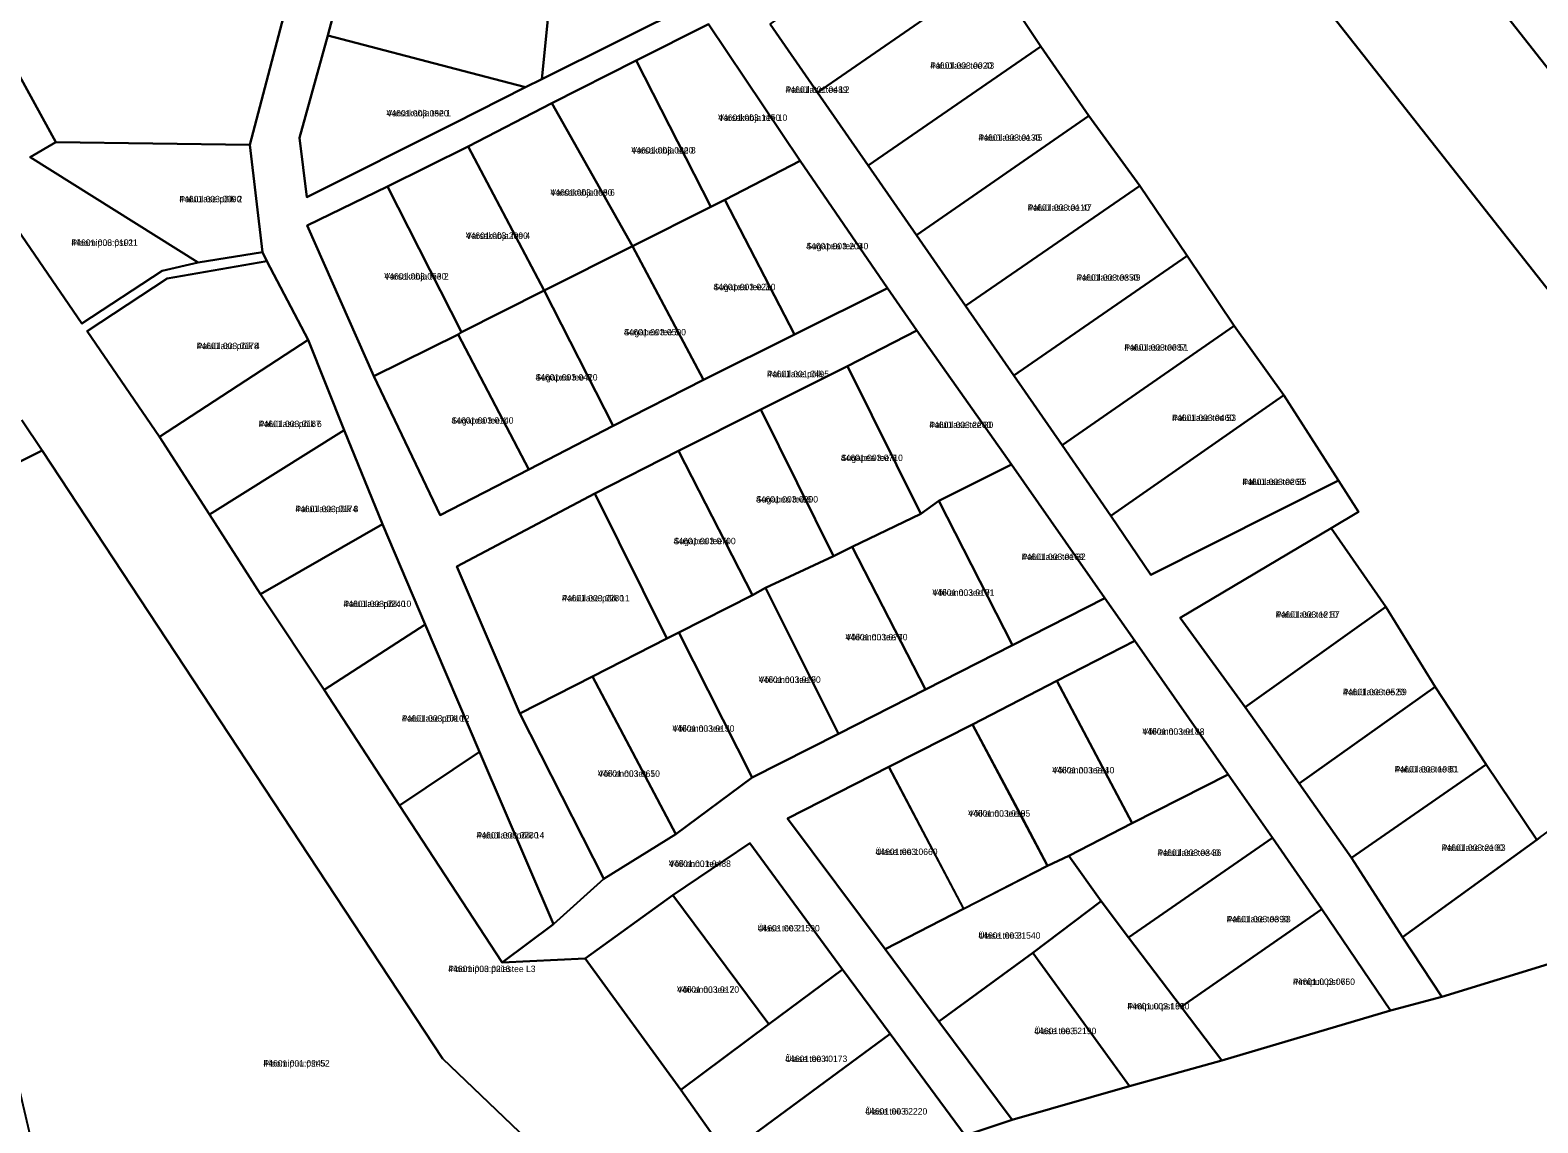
# Model space of a CAD drawing. Extents: x 551843 to 558501, y 6589003 to 6595718.
# Drawn here: x 553540.1 to 553892.5, y 6593798.2 to 6594053.6 of the extents above; entities that cross this region are included whole.
import ezdxf

# ---------------------------------------------------------------- set-up
doc = ezdxf.new("R2010")
doc.units = 0
for name, color, linetype in [('L_AADRESS', 7, 'Continuous'), ('PIIR', 7, 'Continuous'), ('TUNNUS', 7, 'Continuous')]:
    doc.layers.add(name, color=color, linetype=linetype)

msp = doc.modelspace()

# ---------------------------------------------------------------- linework, layer by layer
at = {"layer": 'PIIR'}
for points in [[(554441.09, 6593299.31), (554261.19, 6593527.78), (554141.98, 6593679.18), (554122.61, 6593703.78), (554013.74, 6593842.05), (553788.87, 6594127.63), (553766.28, 6594156.32), (553814.68, 6594146.58), (553836.64, 6594118.69), (553980.12, 6593936.47), (554062.14, 6593832.31), (554258.75, 6593582.61), (554309.59, 6593518.04), (554467.93, 6593316.95)], [(553892.97, 6593864.88), (553892.29, 6593864.39), (553880.45, 6593881.96), (553868.51, 6593900.1), (553857.01, 6593918.79), (553844.19, 6593937.25), (553850.61, 6593941.05), (553845.91, 6593948.34), (553833.12, 6593968.28), (553821.56, 6593984.48), (553810.54, 6594000.86), (553799.51, 6594017.22), (553787.57, 6594033.61), (553776.34, 6594049.78), (553764.77, 6594067.21), (553753.75, 6594083.63), (553742.72, 6594099.83), (553731.62, 6594116.26), (553721.36, 6594131.07), (553708.43, 6594145.93), (553788.87, 6594127.63), (554013.74, 6593842.05)], [(553615.73, 6594075.44), (553609.64, 6594052.38), (553603.07, 6594028.45), (553604.73, 6594014.55), (553639.11, 6594031.84), (553655.85, 6594040.27), (553659.7, 6594042.2), (553695.38, 6594059.93)], [(553698.63, 6594055.04), (553681.75, 6594046.52), (553662.01, 6594036.55), (553642.5, 6594026.43), (553623.58, 6594017.08), (553604.81, 6594007.97), (553620.45, 6593972.72), (553635.95, 6593940.23), (553656.68, 6593950.93), (553676.33, 6593961.17), (553697.49, 6593971.89), (553718.72, 6593982.45), (553740.52, 6593993.29), (553747.34, 6593983.4), (553731.11, 6593975.09), (553710.88, 6593964.97), (553691.64, 6593955.3), (553672.07, 6593945.34), (553639.84, 6593928.27), (553654.54, 6593893.89), (553674.15, 6593855.27), (553662.45, 6593844.66), (553645.13, 6593884.97), (553632.46, 6593914.73), (553622.47, 6593938.12), (553613.5, 6593960.12), (553605.06, 6593981.24), (553595.39, 6593999.6), (553594.41, 6594001.73), (553591.42, 6594026.8), (553600.85, 6594062.74)], [(553713.09, 6594055.03), (553724.14, 6594039.02), (553736, 6594021.96), (553747.31, 6594005.74), (553758.71, 6593989.19), (553770.02, 6593972.89), (553781.32, 6593956.58), (553792.68, 6593940.06), (553802.05, 6593926.33), (553845.91, 6593948.34), (553850.61, 6593941.05), (553844.19, 6593937.25), (553808.87, 6593916.22), (553824.08, 6593895.34), (553836.71, 6593877.56), (553848.98, 6593860.12), (553860.87, 6593841.59), (553870.08, 6593827.69), (553858.07, 6593824.49), (553842.01, 6593848.12), (553830.45, 6593864.83), (553820.09, 6593879.67), (553798.32, 6593910.89), (553791.28, 6593920.84), (553769.44, 6593952.07), (553747.34, 6593983.4), (553740.52, 6593993.29), (553720.07, 6594023.04), (553698.63, 6594055.04)], [(553520.12, 6594031.76), (553552.16, 6593985.04), (553570.97, 6593997.38), (553579.37, 6593999.32), (553594.41, 6594001.73), (553595.39, 6593999.6), (553572.1, 6593995.56), (553553.44, 6593983.25), (553570.3, 6593958.54), (553581.99, 6593940.44), (553593.91, 6593921.8), (553608.8, 6593899.44), (553626.41, 6593872.42), (553650.42, 6593835.7), (553669.81, 6593836.61), (553692.18, 6593805.9), (553702.89, 6593790.78)], [(553538.17, 6593962.48), (553542.86, 6593955.37), (553507.01, 6593937.53)], [(553668.84, 6593782.29), (553636.48, 6593813.23), (553542.86, 6593955.37), (553538.17, 6593962.48)], [(553758.61, 6593795.24), (553769.62, 6593798.93), (553797.08, 6593806.79), (553818.66, 6593812.78), (553858.07, 6593824.49), (553870.08, 6593827.69), (553909.89, 6593839.88), (553918.7, 6593842.58), (554046.25, 6593756.59)]]:
    msp.add_lwpolyline(points, dxfattribs=at)
for points in [[(553991.37, 6593974.95), (553980.12, 6593936.47), (553836.64, 6594118.69), (553883.5, 6594111.54), (553877.52, 6594090.46), (553906.3, 6594061.6), (553904.05, 6594050.84), (553942.36, 6594039.81), (553951.03, 6593995.91), (553962.77, 6593981.08)], [(553676.99, 6594087.38), (553695.38, 6594059.93), (553659.7, 6594042.2), (553662.14, 6594066.34), (553665.05, 6594095.15)], [(553596.23, 6594083.84), (553600.85, 6594062.74), (553591.42, 6594026.8), (553546.1, 6594027.45), (553537.6, 6594042.92), (553534.09, 6594049.22), (553535.15, 6594049.87), (553533.9, 6594052.21), (553526.78, 6594065.5), (553527.74, 6594065.97), (553546.27, 6594075.04), (553566.95, 6594081.08), (553572.4, 6594082.6), (553594.49, 6594083.76)], [(553713.09, 6594055.03), (553753.75, 6594083.63), (553764.77, 6594067.21), (553724.11, 6594039.02)], [(553615.73, 6594075.44), (553647.88, 6594069.14), (553662.14, 6594066.34), (553659.7, 6594042.2), (553655.85, 6594040.27), (553641.25, 6594044.1), (553609.64, 6594052.38)], [(553724.14, 6594039.02), (553764.77, 6594067.21), (553776.34, 6594049.78), (553736, 6594021.96)], [(553641.25, 6594044.1), (553655.85, 6594040.27), (553639.11, 6594031.84), (553604.73, 6594014.55), (553603.07, 6594028.45), (553609.64, 6594052.38)], [(553699.21, 6594012.33), (553681.75, 6594046.52), (553698.63, 6594055.04), (553720.07, 6594023.04), (553702.47, 6594013.97)], [(553776.34, 6594049.78), (553787.57, 6594033.61), (553747.31, 6594005.74), (553736, 6594021.96)], [(553680.9, 6594003.12), (553662.01, 6594036.55), (553681.75, 6594046.52), (553699.21, 6594012.33)], [(553520.12, 6594031.76), (553537.6, 6594042.92), (553546.1, 6594027.45), (553540.07, 6594023.91), (553579.37, 6593999.32), (553570.97, 6593997.38), (553552.16, 6593985.04)], [(553660.27, 6593992.77), (553642.5, 6594026.43), (553662.01, 6594036.55), (553680.9, 6594003.12)], [(553747.31, 6594005.74), (553787.57, 6594033.61), (553799.51, 6594017.22), (553758.71, 6593989.19)], [(553591.42, 6594026.8), (553594.41, 6594001.73), (553579.36, 6593999.33), (553540.11, 6594023.91), (553546.1, 6594027.45)], [(553640.93, 6593983.01), (553623.58, 6594017.08), (553642.5, 6594026.43), (553660.27, 6593992.77)], [(553718.72, 6593982.45), (553702.47, 6594013.97), (553720.07, 6594023.04), (553740.52, 6593993.29)], [(553620.45, 6593972.72), (553604.81, 6594007.97), (553623.58, 6594017.08), (553640.93, 6593983.01), (553640.1, 6593982.46)], [(553758.71, 6593989.19), (553799.51, 6594017.22), (553810.54, 6594000.86), (553770.02, 6593972.89)], [(553697.49, 6593971.89), (553680.9, 6594003.12), (553699.21, 6594012.33), (553702.47, 6594013.97), (553718.72, 6593982.45)], [(553676.33, 6593961.17), (553660.27, 6593992.77), (553680.9, 6594003.12), (553697.49, 6593971.89)], [(553553.44, 6593983.25), (553572.1, 6593995.56), (553595.39, 6593999.6), (553605.06, 6593981.24), (553570.3, 6593958.54)], [(553770.02, 6593972.89), (553810.54, 6594000.86), (553821.56, 6593984.48), (553781.32, 6593956.58)], [(553656.68, 6593950.93), (553640.1, 6593982.46), (553640.93, 6593983.01), (553660.27, 6593992.77), (553676.33, 6593961.17)], [(553635.95, 6593940.23), (553620.45, 6593972.72), (553640.1, 6593982.46), (553656.68, 6593950.93)], [(553747.34, 6593983.4), (553769.44, 6593952.07), (553752.48, 6593943.57), (553748.27, 6593940.55), (553731.11, 6593975.09)], [(553781.32, 6593956.58), (553821.56, 6593984.48), (553833.12, 6593968.28), (553792.68, 6593940.06)], [(553570.3, 6593958.54), (553605.06, 6593981.24), (553613.5, 6593960.12), (553581.99, 6593940.44)], [(553731.11, 6593975.09), (553748.27, 6593940.55), (553732.27, 6593932.82), (553727.85, 6593930.66), (553710.88, 6593964.97)], [(553792.68, 6593940.06), (553833.12, 6593968.28), (553845.91, 6593948.34), (553802.05, 6593926.33)], [(553710.88, 6593964.97), (553727.85, 6593930.66), (553711.99, 6593923.23), (553708.92, 6593921.58), (553691.64, 6593955.3)], [(553581.99, 6593940.44), (553613.5, 6593960.12), (553622.47, 6593938.12), (553593.91, 6593921.8)], [(553514.88, 6593903.23), (553507.01, 6593937.53), (553542.86, 6593955.37), (553636.48, 6593813.23), (553668.84, 6593782.29), (553682.2, 6593770.11), (553662.08, 6593754.91), (553645.43, 6593779.86), (553641.35, 6593785.23), (553628.15, 6593776.12), (553631.77, 6593770.74), (553620.41, 6593763.16), (553618.37, 6593761.87), (553614.56, 6593767.34), (553601.23, 6593758.1), (553604.99, 6593752.88), (553591.37, 6593743.76), (553608.02, 6593718.81), (553573.18, 6593693.61), (553568.93, 6593701.92), (553562.79, 6593698.22), (553544.92, 6593774.7), (553535.42, 6593815.33), (553523, 6593868.46)], [(553691.64, 6593955.3), (553708.92, 6593921.58), (553691.71, 6593912.82), (553688.94, 6593911.4), (553672.07, 6593945.34)], [(553752.48, 6593943.57), (553769.44, 6593952.07), (553791.28, 6593920.84), (553769.71, 6593909.88)], [(553672.07, 6593945.34), (553688.94, 6593911.4), (553671.57, 6593902.55), (553654.54, 6593893.89), (553639.84, 6593928.27)], [(553732.27, 6593932.82), (553748.27, 6593940.55), (553752.48, 6593943.57), (553769.71, 6593909.88), (553749.35, 6593899.48)], [(553622.47, 6593938.12), (553632.46, 6593914.73), (553608.8, 6593899.44), (553593.91, 6593921.8)], [(553824.08, 6593895.34), (553808.87, 6593916.22), (553844.19, 6593937.25), (553857.01, 6593918.79)], [(553727.85, 6593930.66), (553732.27, 6593932.82), (553749.35, 6593899.48), (553729.04, 6593889.13), (553711.99, 6593923.23)], [(553691.71, 6593912.82), (553708.92, 6593921.58), (553711.99, 6593923.23), (553729.04, 6593889.13), (553708.86, 6593878.97)], [(553650.42, 6593835.7), (553662.45, 6593844.66), (553674.15, 6593855.27), (553691.03, 6593865.68), (553708.86, 6593878.97), (553729.04, 6593889.13), (553749.35, 6593899.48), (553769.71, 6593909.88), (553791.28, 6593920.84), (553798.32, 6593910.89), (553780.06, 6593901.5), (553760.37, 6593891.35), (553740.8, 6593881.41), (553717.13, 6593869.32), (553739.93, 6593838.82), (553752.52, 6593821.87), (553769.62, 6593798.93), (553758.61, 6593795.24), (553741.11, 6593818.98), (553730.01, 6593834.09), (553708.34, 6593863.55), (553690.29, 6593851.46), (553669.81, 6593836.61)], [(553824.08, 6593895.34), (553857.01, 6593918.79), (553868.51, 6593900.1), (553836.71, 6593877.56)], [(553645.13, 6593884.97), (553626.41, 6593872.42), (553608.8, 6593899.44), (553632.46, 6593914.73)], [(553671.57, 6593902.55), (553688.94, 6593911.4), (553691.71, 6593912.82), (553708.86, 6593878.97), (553691.03, 6593865.68)], [(553798.32, 6593910.89), (553820.09, 6593879.67), (553797.66, 6593868.25), (553780.06, 6593901.5)], [(553671.57, 6593902.55), (553691.03, 6593865.68), (553674.15, 6593855.27), (553654.54, 6593893.89)], [(553780.06, 6593901.5), (553797.66, 6593868.25), (553782.9, 6593860.62), (553777.92, 6593858.3), (553760.37, 6593891.35)], [(553836.71, 6593877.56), (553868.51, 6593900.1), (553880.45, 6593881.96), (553848.98, 6593860.12)], [(553740.8, 6593881.41), (553760.37, 6593891.35), (553772.09, 6593869.27), (553777.89, 6593858.26), (553758.32, 6593848.22)], [(553645.13, 6593884.97), (553662.45, 6593844.66), (553650.42, 6593835.7), (553626.41, 6593872.42)], [(553740.8, 6593881.41), (553758.25, 6593848.21), (553739.93, 6593838.82), (553717.13, 6593869.32)], [(553790.43, 6593850.03), (553782.9, 6593860.62), (553797.66, 6593868.25), (553820.09, 6593879.67), (553830.45, 6593864.83), (553796.85, 6593841.55)], [(553848.98, 6593860.12), (553880.45, 6593881.96), (553892.29, 6593864.39), (553860.87, 6593841.59)], [(553870.08, 6593827.69), (553860.87, 6593841.59), (553892.29, 6593864.39), (553892.97, 6593864.88), (553900.13, 6593870.11), (553918.7, 6593842.58), (553909.89, 6593839.88)], [(553708.34, 6593863.55), (553730.01, 6593834.09), (553712.78, 6593821.28), (553690.29, 6593851.46)], [(553830.45, 6593864.83), (553842.01, 6593848.12), (553809.13, 6593825.35), (553796.85, 6593841.55)], [(553758.25, 6593848.21), (553777.92, 6593858.3), (553782.9, 6593860.62), (553790.43, 6593850.03), (553774.46, 6593837.94), (553752.52, 6593821.87), (553739.93, 6593838.82)], [(553690.29, 6593851.46), (553712.78, 6593821.28), (553692.18, 6593805.9), (553669.81, 6593836.61)], [(553790.43, 6593850.03), (553796.85, 6593841.55), (553809.13, 6593825.35), (553818.66, 6593812.78), (553797.08, 6593806.79), (553774.46, 6593837.94)], [(553858.07, 6593824.49), (553818.66, 6593812.78), (553809.13, 6593825.35), (553842.01, 6593848.12)], [(553774.46, 6593837.94), (553797.08, 6593806.79), (553769.62, 6593798.93), (553752.52, 6593821.87)], [(553692.18, 6593805.9), (553712.78, 6593821.28), (553730.01, 6593834.09), (553741.11, 6593818.98), (553702.89, 6593790.78)], [(553741.11, 6593818.98), (553758.61, 6593795.24), (553710.04, 6593781.31), (553702.89, 6593790.78)]]:
    msp.add_lwpolyline(points, close=True, dxfattribs=at)

# ---------------------------------------------------------------- texts
at = {"layer": 'L_AADRESS'}
for s, p in [('Paluülase tee 43', (553750.48, 6594044.59)), ('Paluülase tee L2', (553716.68, 6594038.96)), ('Varsakabja tee 1', (553623.39, 6594033.46)), ('Varsakabja tee 10', (553700.91, 6594032.41)), ('Paluülase tee 45', (553761.76, 6594027.76)), ('Varsakabja tee 8', (553680.61, 6594024.79)), ('Paluülase põik 2', (553574.96, 6594013.39)), ('Varsakabja tee 6', (553661.7, 6594014.94)), ('Paluülase tee 47', (553773.26, 6594011.4)), ('Varsakabja tee 4', (553641.93, 6594004.83)), ('Ploomipuu pst 21', (553549.74, 6594003.21)), ('Sugapea tee 9', (553721.5, 6594002.4)), ('Varsakabja tee 2', (553622.87, 6593995.33)), ('Paluülase tee 49', (553784.69, 6593995.05)), ('Sugapea tee 7', (553699.81, 6593992.84)), ('Sugapea tee 5', (553678.88, 6593982.28)), ('Paluülase põik 4', (553579.01, 6593979.07)), ('Paluülase tee 51', (553795.86, 6593978.72)), ('Sugapea tee 3', (553658.21, 6593971.73)), ('Paluülase põik', (553712.32, 6593972.5)), ('Paluülase tee 53', (553807.02, 6593962.27)), ('Paluülase põik 6', (553593.52, 6593960.84)), ('Sugapea tee 1', (553638.57, 6593961.64)), ('Paluülase tee 30', (553750.27, 6593960.61)), ('Sugapea tee 8', (553729.58, 6593952.91)), ('Paluülase tee 55', (553823.45, 6593947.3)), ('Sugapea tee 6', (553709.75, 6593943.21)), ('Paluülase põik 8', (553602.07, 6593940.96)), ('Sugapea tee 4', (553690.5, 6593933.46)), ('Paluülase tee 32', (553771.88, 6593929.78)), ('Paluülase põik 11', (553664.39, 6593920.09)), ('Võikannu tee 9', (553750.99, 6593921.41)), ('Paluülase põik 10', (553613.33, 6593918.78)), ('Paluülase tee 57', (553831.25, 6593916.29)), ('Võikannu tee 7', (553730.67, 6593911)), ('Võikannu tee 5', (553710.38, 6593901.05)), ('Paluülase tee 59', (553846.93, 6593898.17)), ('Paluülase põik 12', (553626.96, 6593891.99)), ('Võikannu tee 3', (553690.21, 6593889.64)), ('Võikannu tee 12', (553800.08, 6593888.93)), ('Võikannu tee 1', (553672.79, 6593879.1)), ('Võikannu tee 10', (553779.01, 6593879.89)), ('Paluülase tee 61', (553859.05, 6593880.11)), ('Võikannu tee 8', (553759.34, 6593869.79)), ('Paluülase põik 14', (553644.43, 6593864.68)), ('Ülase tee 1', (553737.69, 6593860.82)), ('Paluülase tee 36', (553803.63, 6593860.61)), ('Paluülase tee 63', (553870.03, 6593861.78)), ('Võikannu tee', (553689.38, 6593858.04)), ('Ülase tee 2', (553710.15, 6593842.95)), ('Paluülase tee 38', (553819.8, 6593845.09)), ('Ülase tee 3', (553761.74, 6593841.25)), ('Ploomipuu puiestee L3', (553637.82, 6593833.45)), ('Võikannu tee 2', (553691.3, 6593828.61)), ('Pirnipuu pst 65', (553835.26, 6593830.45)), ('Pirnipuu pst 63', (553796.56, 6593824.72)), ('Ülase tee 5', (553774.8, 6593818.94)), ('Ploomipuu pst 52', (553594.61, 6593811.37)), ('Ülase tee 4', (553716.59, 6593812.44)), ('Ülase tee 6', (553735.29, 6593800.15))]:
    msp.add_text(s, height=1.5, dxfattribs=at).set_placement(p)
at = {"layer": 'TUNNUS'}
for s, p in [('44601:003:0020', (553750.48, 6594044.59)), ('44601:001:0489', (553716.68, 6594038.96)), ('44601:003:0820', (553623.39, 6594033.46)), ('44601:003:1150', (553700.91, 6594032.41)), ('44601:003:0130', (553761.76, 6594027.76)), ('44601:003:0220', (553680.61, 6594024.79)), ('44601:003:0090', (553574.96, 6594013.39)), ('44601:003:0080', (553661.7, 6594014.94)), ('44601:003:0110', (553773.26, 6594011.4)), ('44601:003:2090', (553641.93, 6594004.83)), ('44601:003:0191', (553549.74, 6594003.21)), ('44601:003:2040', (553721.5, 6594002.4)), ('44601:003:0530', (553622.87, 6593995.33)), ('44601:003:0350', (553784.69, 6593995.05)), ('44601:003:0210', (553699.81, 6593992.84)), ('44601:003:0500', (553678.88, 6593982.28)), ('44601:003:0178', (553579.01, 6593979.07)), ('44601:003:0087', (553795.86, 6593978.72)), ('44601:003:0420', (553658.21, 6593971.73)), ('44601:001:0495', (553712.32, 6593972.5)), ('44601:003:0460', (553807.02, 6593962.27)), ('44601:003:0187', (553593.52, 6593960.84)), ('44601:003:0140', (553638.57, 6593961.64)), ('44601:003:2200', (553750.27, 6593960.61)), ('44601:003:0710', (553729.58, 6593952.91)), ('44601:003:0260', (553823.45, 6593947.3)), ('44601:003:0200', (553709.75, 6593943.21)), ('44601:003:0174', (553602.07, 6593940.96)), ('44601:003:0700', (553690.5, 6593933.46)), ('44601:003:0169', (553771.88, 6593929.78)), ('44601:003:0280', (553664.39, 6593920.09)), ('44601:003:0171', (553750.99, 6593921.41)), ('44601:003:0240', (553613.33, 6593918.78)), ('44601:003:1210', (553831.25, 6593916.29)), ('44601:003:0740', (553730.67, 6593911)), ('44601:003:0190', (553710.38, 6593901.05)), ('44601:003:0520', (553846.93, 6593898.17)), ('44601:003:1010', (553626.96, 6593891.99)), ('44601:003:0150', (553690.21, 6593889.64)), ('44601:003:0188', (553800.08, 6593888.93)), ('44601:003:0650', (553672.79, 6593879.1)), ('44601:003:2240', (553779.01, 6593879.89)), ('44601:003:1980', (553859.05, 6593880.11)), ('44601:003:0195', (553759.34, 6593869.79)), ('44601:003:0230', (553644.43, 6593864.68)), ('44601:003:0660', (553737.69, 6593860.82)), ('44601:003:0340', (553803.63, 6593860.61)), ('44601:003:2100', (553870.03, 6593861.78)), ('44601:001:0488', (553689.38, 6593858.04)), ('44601:003:1590', (553710.15, 6593842.95)), ('44601:003:0390', (553819.8, 6593845.09)), ('44601:003:1540', (553761.74, 6593841.25)), ('44601:003:0216', (553637.82, 6593833.45)), ('44601:003:0170', (553691.3, 6593828.61)), ('44601:003:0760', (553835.26, 6593830.45)), ('44601:003:1910', (553796.56, 6593824.72)), ('44601:003:2190', (553774.8, 6593818.94)), ('44601:001:0245', (553594.61, 6593811.37)), ('44601:003:0173', (553716.59, 6593812.44)), ('44601:003:2220', (553735.29, 6593800.15))]:
    msp.add_text(s, height=1.5, dxfattribs=at).set_placement(p)

doc.saveas('drawing.dxf')
